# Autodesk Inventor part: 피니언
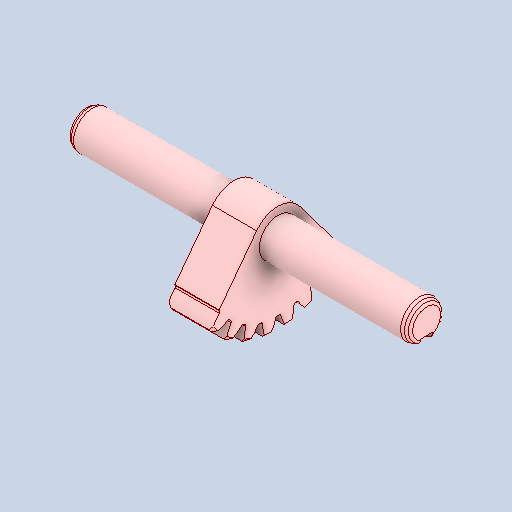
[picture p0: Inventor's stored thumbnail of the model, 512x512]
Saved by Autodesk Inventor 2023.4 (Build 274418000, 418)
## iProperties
Created: 2024-05
Part Number: 피니언
Material: 강철, 탄소
Document SubType Name: Modeling
Designer: edu-40
Density: 7.85 g/cm^3
Appearance: 기본값
Author: jhkim
Sending System: Autodesk Inventor 2025
Preprocessor: ST-DEVELOPER v20
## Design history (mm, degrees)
feature "솔리드1"
node "솔리드2"
